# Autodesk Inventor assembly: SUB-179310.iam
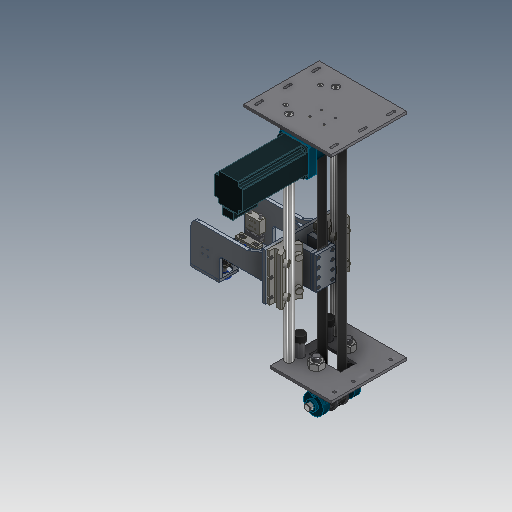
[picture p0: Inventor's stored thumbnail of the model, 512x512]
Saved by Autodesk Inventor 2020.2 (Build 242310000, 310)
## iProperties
Created: 1999-11
Part Number: SUB-179310.iam
Document SubType Name: Assembly
Designer: sspink
Mass: 67353.5 g
Surface Area: 21686.1 cm^2
Volume: 12770.4 cm^3
Density: 5.27418 g/cm^3
Control State: 0
Master: False
Checked Out: False
Shininess: 0.0
Length Units: 11269
Angle Units: 11279
Time Units: 11290
Mass Units: 11283
Length Display Precision: 3
Angle Display Precision: 2
Compacted: True
Dimensions: 1051,2x644,7x575,4 mm
Mass: 67,353 kg
DocNumber: SUB-179310.iam
Folder: 01 - Themengebiete\Simplification\01 - Packaging machine\
VDS_Category: 3D Komponenten
VDS_NumSchm: Kein
Density: 0.0
Volumn: 0.0
Area: 0.0
PropertySet Name: Model Information
Author: sspink
Revision Number: -
Title: SUB-179310
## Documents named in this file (22)
- D:\07 - DEMODATEN\OTX 2019 - Dataset - UPDATE - Dez2019\Designs\07-Packing machine\SUB-179310.iam
- D:\07 - DEMODATEN\OTX 2019 - Dataset - UPDATE - Dez2019\Designs\07-Packing machine\Parts\ADSK-011674.ipt
- D:\07 - DEMODATEN\OTX 2019 - Dataset - UPDATE - Dez2019\Designs\07-Packing machine\Parts\ADSK-011397.ipt
- D:\07 - DEMODATEN\OTX 2019 - Dataset - UPDATE - Dez2019\Designs\07-Packing machine\Parts\ADSK-011751.ipt
- D:\07 - DEMODATEN\OTX 2019 - Dataset - UPDATE - Dez2019\Designs\07-Packing machine\Parts\ADSK-011675.ipt
- D:\07 - DEMODATEN\OTX 2019 - Dataset - UPDATE - Dez2019\Designs\07-Packing machine\Parts\ADSK-011305.ipt
- D:\07 - DEMODATEN\OTX 2019 - Dataset - UPDATE - Dez2019\Designs\07-Packing machine\500381.iam
- D:\07 - DEMODATEN\OTX 2019 - Dataset - UPDATE - Dez2019\Designs\07-Packing machine\Parts\ADSK-011314.ipt
- D:\07 - DEMODATEN\OTX 2019 - Dataset - UPDATE - Dez2019\Designs\07-Packing machine\Parts\ADSK-011773.ipt
- D:\07 - DEMODATEN\OTX 2019 - Dataset - UPDATE - Dez2019\Designs\07-Packing machine\Parts\ADSK-011343.ipt
- D:\07 - DEMODATEN\OTX 2019 - Dataset - UPDATE - Dez2019\Designs\07-Packing machine\Parts\ADSK-011811.ipt
- D:\07 - DEMODATEN\OTX 2019 - Dataset - UPDATE - Dez2019\Designs\07-Packing machine\Parts\ADSK-011235.ipt
- D:\07 - DEMODATEN\OTX 2019 - Dataset - UPDATE - Dez2019\Designs\07-Packing machine\A103445.iam
- D:\07 - DEMODATEN\OTX 2019 - Dataset - UPDATE - Dez2019\Content Center Files\de-DE\ISO 10642(1)\ISO 10642 - M8x25.ipt
- D:\07 - DEMODATEN\OTX 2019 - Dataset - UPDATE - Dez2019\Content Center Files\de-DE\ISO 10642(1)\ISO 10642 - M12x35.ipt
- D:\07 - DEMODATEN\OTX 2019 - Dataset - UPDATE - Dez2019\Content Center Files\de-DE\DIN 125-1  B\DIN 125-1 - B 8,4.ipt
- D:\07 - DEMODATEN\OTX 2019 - Dataset - UPDATE - Dez2019\Content Center Files\de-DE\DIN EN 24 017\ISO 4017 - M8 x 16DIN EN.ipt
- D:\07 - DEMODATEN\OTX 2019 - Dataset - UPDATE - Dez2019\Designs\07-Packing machine\ADSK-014167.iam
- D:\07 - DEMODATEN\OTX 2019 - Dataset - UPDATE - Dez2019\Content Center Files\de-DE\ISO 4032(2)\ISO 4032 - M30 - ISO.ipt
- D:\07 - DEMODATEN\OTX 2019 - Dataset - UPDATE - Dez2019\Content Center Files\de-DE\ISO 2491 - A\ISO 2491 - A  6 x 4 x 32.ipt
- D:\07 - DEMODATEN\OTX 2019 - Dataset - UPDATE - Dez2019\Designs\07-Packing machine\ADSK-014170.iam
- D:\07 - DEMODATEN\OTX 2019 - Dataset - UPDATE - Dez2019\Designs\07-Packing machine\Parts\ADSK-014198.ipt
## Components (45 placed, 21 different names)
1. ADSK-011343:1 — Mate:15, Mate:26, Mate:27, Mate:28, Insert:19, Insert:20, Mate:47, Mate:48, Passend:67, Passend:68, Passend:85, Passend:86
2. ADSK-014198:1 — Insert:19, Passend:59, Passend:90
3. ADSK-014198:2 — Mate:31, Insert:20, Passend:60, Passend:91
4. ADSK-011314:3 — Insert:11, Flush:8, Mate:35, Passend:92
5. ADSK-011314:4 — Insert:10, Mate:34, Flush:8, Passend:93
6. ADSK-011773:3 — Insert:10, Mate:13
7. ADSK-011773:4 — Insert:11, Mate:13, Passend:104
8. ADSK-011305:2 — Passend:103, Passend:104, Passend:105, Passend:106, Passend:107, Passend:111, Passend:114
9. ADSK-011811:1 — Insert:13, Insert:14, Mate:16, Mate:17, Angular, Mate:24, Passend:87, Passend:88, Passend:89, Passend:108
10. 1.5 inch timing belt.ipt:1 — Mate:24, Fluchtend:9, Passend:103, Passend:109, Passend:110, Passend:112, Passend:113
11. 500381:1 [sub-assembly] — Mate:15, Insert:13, Insert:14, Passend:67, Passend:68, Passend:70, Passend:72, Passend:74, Passend:76, Passend:87, Passend:88, Passend:89
12. A103445:1 [sub-assembly] — Mate:16, Mate:17, Angular
13. ADSK-011397:1 — Mate:31, Mate:34, Mate:35, Insert:29, Insert:30, Passend:59, Passend:60, Passend:92, Passend:93, Passend:95, Passend:97, Fluchtend:9
14. ADSK-011674:1 — Mate:47, Insert:26, Passend:86
15. ADSK-011674:2 — Mate:48, Insert:25, Passend:85
16. ADSK-011751:1 — Insert:26
17. ADSK-011751:2 — Insert:25
18. ADSK-011675:1 — Insert:27, Insert:29
19. ADSK-011675:2 — Insert:28, Insert:30
20. ADSK-011751:3 — Insert:28, STROKE
21. ADSK-011751:4 — Insert:27
22. ADSK-014170:1 [sub-assembly] — Passend:108, Passend:109, Passend:110
23. ADSK-014170:2 [sub-assembly] — Passend:111, Passend:112, Passend:113, Passend:114
24. ISO 2491 A A  6 x 4 x 32:1 — Passend:105, Passend:106, Passend:107
25. ISO 10642 M8x25:1
26. ISO 10642 M8x25:2
27. ISO 10642 M12x35:1
28. ISO 10642 M12x35:2
29. ISO 10642 M12x35:3
30. ISO 10642 M12x35:4
31. ISO 10642 M8x25:3
32. ISO 10642 M8x25:4
33. DIN 125-1 B B 8,4:1 — Passend:70, Passend:78, Passend:80, Passend:82, Passend:84
34. DIN 125-1 B B 8,4:2 — Passend:72
35. DIN 125-1 B B 8,4:3 — Passend:74
36. DIN 125-1 B B 8,4:4 — Passend:76
37. DIN EN 24017 M8 x 16:1 — Passend:78
38. DIN EN 24017 M8 x 16:2 — Passend:80
39. DIN EN 24017 M8 x 16:3 — Passend:82
40. DIN EN 24017 M8 x 16:4 — Passend:84
41. ADSK-014167:1 [sub-assembly] — Passend:90, Passend:91, STROKE
42. ISO 4032 M30:1 — Passend:95
43. ISO 4032 M30:2 — Passend:97
44. ISO 4032 M30:3
45. ISO 4032 M30:4
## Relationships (64: Mate 49, Insert 12, Flush 2, Angle 1)
- STROKE [Mate]: ADSK-011751:3 ↔ ADSK-014167:1
- Insert:10: ADSK-011314:4 ↔ ADSK-011773:3
- Insert:11: ADSK-011314:3 ↔ ADSK-011773:4
- Mate:13: ADSK-011773:3 ↔ ADSK-011773:4
- Mate:15: ADSK-011343:1 ↔ 500381:1
- Insert:13: ADSK-011811:1 ↔ 500381:1
- Insert:14: ADSK-011811:1 ↔ 500381:1
- Mate:16: ADSK-011811:1 ↔ A103445:1
- Mate:17: ADSK-011811:1 ↔ A103445:1
- Angular [Angle]: ADSK-011811:1 ↔ A103445:1
- Mate:24: ADSK-011811:1 ↔ 1.5 inch timing belt.ipt:1
- Mate:26: ADSK-011343:1
- Mate:27: ADSK-011343:1
- Mate:28: ADSK-011343:1
- Mate:31: ADSK-014198:2 ↔ ADSK-011397:1
- Mate:34: ADSK-011314:4 ↔ ADSK-011397:1
- Flush:8: ADSK-011314:3 ↔ ADSK-011314:4
- Mate:35: ADSK-011314:3 ↔ ADSK-011397:1
- Insert:19: ADSK-011343:1 ↔ ADSK-014198:1
- Insert:20: ADSK-011343:1 ↔ ADSK-014198:2
- Mate:47: ADSK-011343:1 ↔ ADSK-011674:1
- Mate:48: ADSK-011343:1 ↔ ADSK-011674:2
- Insert:25: ADSK-011674:2 ↔ ADSK-011751:2
- Insert:26: ADSK-011674:1 ↔ ADSK-011751:1
- Insert:27: ADSK-011675:1 ↔ ADSK-011751:4
- Insert:28: ADSK-011675:2 ↔ ADSK-011751:3
- Insert:29: ADSK-011397:1 ↔ ADSK-011675:1
- Insert:30: ADSK-011397:1 ↔ ADSK-011675:2
- Passend:59 [Mate]: ADSK-014198:1 ↔ ADSK-011397:1
- Passend:60 [Mate]: ADSK-014198:2 ↔ ADSK-011397:1
- Passend:67 [Mate]: ADSK-011343:1 ↔ 500381:1
- Passend:68 [Mate]: ADSK-011343:1 ↔ 500381:1
- Passend:70 [Mate]: 500381:1 ↔ DIN 125-1 B B 8,4:1
- Passend:72 [Mate]: 500381:1 ↔ DIN 125-1 B B 8,4:2
- Passend:74 [Mate]: 500381:1 ↔ DIN 125-1 B B 8,4:3
- Passend:76 [Mate]: 500381:1 ↔ DIN 125-1 B B 8,4:4
- Passend:78 [Mate]: DIN 125-1 B B 8,4:1 ↔ DIN EN 24017 M8 x 16:1
- Passend:80 [Mate]: DIN 125-1 B B 8,4:1 ↔ DIN EN 24017 M8 x 16:2
- Passend:82 [Mate]: DIN 125-1 B B 8,4:1 ↔ DIN EN 24017 M8 x 16:3
- Passend:84 [Mate]: DIN 125-1 B B 8,4:1 ↔ DIN EN 24017 M8 x 16:4
- Passend:85 [Mate]: ADSK-011343:1 ↔ ADSK-011674:2
- Passend:86 [Mate]: ADSK-011343:1 ↔ ADSK-011674:1
- Passend:87 [Mate]: ADSK-011811:1 ↔ 500381:1
- Passend:88 [Mate]: ADSK-011811:1 ↔ 500381:1
- Passend:89 [Mate]: ADSK-011811:1 ↔ 500381:1
- Passend:90 [Mate]: ADSK-014198:1 ↔ ADSK-014167:1
- Passend:91 [Mate]: ADSK-014198:2 ↔ ADSK-014167:1
- Passend:92 [Mate]: ADSK-011314:3 ↔ ADSK-011397:1
- Passend:93 [Mate]: ADSK-011314:4 ↔ ADSK-011397:1
- Passend:95 [Mate]: ADSK-011397:1 ↔ ISO 4032 M30:1
- Passend:97 [Mate]: ADSK-011397:1 ↔ ISO 4032 M30:2
- Fluchtend:9 [Flush]: 1.5 inch timing belt.ipt:1 ↔ ADSK-011397:1
- Passend:103 [Mate]: ADSK-011305:2 ↔ 1.5 inch timing belt.ipt:1
- Passend:104 [Mate]: ADSK-011773:4 ↔ ADSK-011305:2
- Passend:105 [Mate]: ADSK-011305:2 ↔ ISO 2491 A A  6 x 4 x 32:1
- Passend:106 [Mate]: ADSK-011305:2 ↔ ISO 2491 A A  6 x 4 x 32:1
- Passend:107 [Mate]: ADSK-011305:2 ↔ ISO 2491 A A  6 x 4 x 32:1
- Passend:108 [Mate]: ADSK-011811:1 ↔ ADSK-014170:1
- Passend:109 [Mate]: 1.5 inch timing belt.ipt:1 ↔ ADSK-014170:1
- Passend:110 [Mate]: 1.5 inch timing belt.ipt:1 ↔ ADSK-014170:1
- Passend:111 [Mate]: ADSK-011305:2 ↔ ADSK-014170:2
- Passend:112 [Mate]: 1.5 inch timing belt.ipt:1 ↔ ADSK-014170:2
- Passend:113 [Mate]: 1.5 inch timing belt.ipt:1 ↔ ADSK-014170:2
- Passend:114 [Mate]: ADSK-011305:2 ↔ ADSK-014170:2
